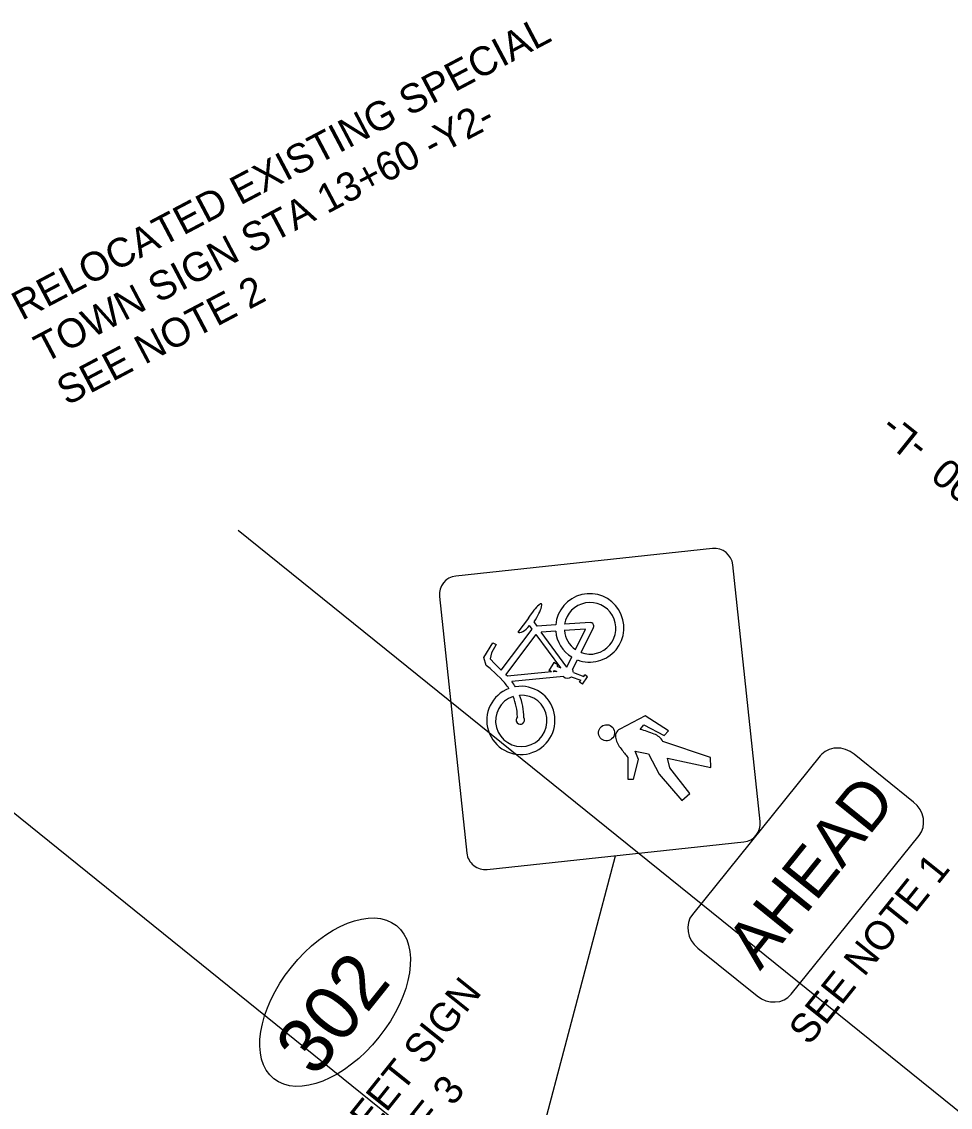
# Model space of a CAD drawing. Extents: x 1487362 to 2061618, y 497428 to 671257.
# Drawn here: x 1488633.1 to 1488736, y 499272.6 to 499392.9 of the extents above; entities that cross this region are included whole.
import ezdxf

# ---------------------------------------------------------------- set-up
doc = ezdxf.new("R2010")
doc.units = 0
for name, color, linetype in [('Exist Sign E', 7, 'Continuous'), ('Exist Sign E Ahead Panel CELL', 7, 'Continuous'), ('Exist Support 1', 7, 'Continuous'), ('Prop Sign E', 7, 'Continuous'), ('Prop Sign E Object Marker CELL', 7, 'Continuous'), ('Scratch_Level_1', 7, 'Continuous'), ('Text', 7, 'Continuous')]:
    doc.layers.add(name, color=color, linetype=linetype)

msp = doc.modelspace()

# ---------------------------------------------------------------- linework, layer by layer
at = {"layer": 'Exist Sign E'}
for p, q in [((1488709.62, 499334.49), (1488681.17, 499331.44)), ((1488714.92, 499304.23), (1488711.87, 499332.68)), ((1488679.36, 499329.19), (1488682.41, 499300.74)), ((1488689.22, 499326.79), (1488688.05, 499325.24)), ((1488689.65, 499325.57), (1488689.34, 499325.97)), ((1488690.2, 499325.9), (1488689.88, 499326.37)), ((1488692.25, 499326.04), (1488690.2, 499325.9)), ((1488696.07, 499326.29), (1488693.23, 499326.1)), ((1488695.07, 499322.97), (1488696.43, 499325.75)), ((1488686.22, 499321.01), (1488689.65, 499325.57)), ((1488686.73, 499320.51), (1488690.09, 499324.97)), ((1488692.81, 499321.28), (1488690.09, 499324.97)), ((1488692.26, 499325.35), (1488690.62, 499325.24)), ((1488693.47, 499321.36), (1488690.62, 499325.24)), ((1488695.56, 499325.57), (1488693.2, 499325.41)), ((1488694.43, 499323.3), (1488695.56, 499325.57)), ((1488684.3, 499322.43), (1488685.29, 499324.04)), ((1488685.64, 499323.86), (1488685.13, 499322.92)), ((1488685.29, 499324.04), (1488685.64, 499323.86)), ((1488684.56, 499321.54), (1488684.3, 499322.43)), ((1488685.13, 499322.92), (1488684.97, 499322.27)), ((1488684.97, 499322.27), (1488685.5, 499321.7)), ((1488693.48, 499321.36), (1488694.04, 499322.49)), ((1488694.12, 499321.09), (1488694.67, 499322.16)), ((1488685, 499321.19), (1488684.56, 499321.54)), ((1488686.24, 499320), (1488685, 499321.19)), ((1488686.22, 499321.01), (1488685.5, 499321.7)), ((1488691.8, 499320.82), (1488691.5, 499321.01)), ((1488691.73, 499320.86), (1488691.5, 499321.01)), ((1488692.06, 499321.85), (1488691.52, 499321)), ((1488692.08, 499320.99), (1488691.96, 499320.82)), ((1488692.38, 499320.87), (1488691.96, 499320.82)), ((1488692.48, 499321.6), (1488692.06, 499321.85)), ((1488692.07, 499320.99), (1488692.38, 499320.87)), ((1488692.49, 499321.6), (1488692.37, 499321.44)), ((1488692.37, 499321.44), (1488692.8, 499321.28)), ((1488686.92, 499320.34), (1488686.73, 499320.51)), ((1488691.8, 499320.82), (1488686.91, 499320.35)), ((1488693.1, 499320.32), (1488687.4, 499319.77)), ((1488693.98, 499320.28), (1488695.05, 499319.9)), ((1488694.21, 499320.75), (1488695.35, 499320.32)), ((1488694.9, 499319.69), (1488695.05, 499319.9)), ((1488695.23, 499319.46), (1488694.9, 499319.69)), ((1488695.23, 499319.46), (1488695.79, 499320.28)), ((1488695.35, 499320.32), (1488695.46, 499320.5)), ((1488695.79, 499320.28), (1488695.46, 499320.5)), ((1488684.66, 499298.93), (1488713.11, 499301.98))]:
    msp.add_line(p, q, dxfattribs=at)
for points in [[(1488701.62, 499314.43), (1488702.03, 499314.94), (1488704.26, 499313.78), (1488704.73, 499314.28), (1488702.17, 499315.97), (1488699.35, 499314.47)], [(1488700.24, 499311.35), (1488700.23, 499308.94), (1488700.88, 499308.92), (1488701.44, 499311.12), (1488701.04, 499312.03), (1488702.53, 499311.76), (1488703.71, 499309.49), (1488706.21, 499306.59), (1488707.12, 499307.34), (1488704.88, 499310.18), (1488704.62, 499311.28), (1488709.44, 499310.23), (1488709.4, 499311.35), (1488704.11, 499313.12)]]:
    msp.add_lwpolyline(points, dxfattribs=at)
for centre, radius, start, end in [((1488709.84, 499332.46), 2.04, 6.1161, 96.1161), ((1488681.39, 499329.41), 2.04, 96.1161, 186.1161), ((1488696.02, 499325.7), 3.79, 248.839, 174.8468), ((1488696.06, 499325.65), 2.86, 249.4542, 170.8979), ((1488696.1, 499325.91), 0.375, 333.8461, 93.8282), ((1488696.02, 499325.7), 3.79, 185.3481, 238.2433), ((1488696.06, 499325.65), 2.86, 184.8373, 235.3657), ((1488693.57, 499320.76), 0.637, 359.8177, 30.2931), ((1488682.16, 499315.81), 5.84, 33.0029, 45.7323), ((1488682.16, 499315.81), 6.56, 30.962, 37.1087), ((1488693.57, 499320.76), 0.637, 222.9807, 310.8196), ((1488688.39, 499315.45), 3.78, 110.6416, 99.1992), ((1488688.44, 499315.4), 2.85, 108.533, 93.6979), ((1488682.16, 499315.81), 5.84, 0.362, 23.0874), ((1488682.16, 499315.81), 6.56, 359.5723, 21.7588), ((1488688.33, 499315.5), 0.471, 133.5219, 32.8623), ((1488712.89, 499304.01), 2.04, 276.1161, 6.1161), ((1488684.44, 499300.96), 2.04, 186.1161, 276.1161)]:
    msp.add_arc(centre, radius, start, end, dxfattribs=at)
for centre, major_axis, ratio, start_param, end_param in [((1488689.54, 499326.57), (1.14, 1.79), 0.185356, 4.712389, 7.853982), ((1488688.87, 499326.33), (0.83, 1.1), 0.433994, 3.141593, 4.712389), ((1488699.74, 499313.69), (-0.683, 0.551), 0.999989, 5.856088, 7.245133), ((1488699.93, 499306.7), (-6.16, 4.97), 0.999989, 4.973098, 5.17626), ((1488702.55, 499312.24), (1.4, -1.13), 0.999989, 1.193544, 1.911048), ((1488701.5, 499314.08), (-2.08, 1.68), 0.999989, 0.918357, 1.400152), ((1488716.72, 499324.96), (-16.64, 13.42), 0.999989, 1.312025, 1.368782)]:
    msp.add_ellipse(centre, major_axis=major_axis, ratio=ratio, start_param=start_param, end_param=end_param, dxfattribs=at)
msp.add_ellipse((1488697.88, 499314.08), major_axis=(0.696, -0.561), ratio=0.999989, dxfattribs=at)
at = {"layer": 'Exist Sign E Ahead Panel CELL'}
for p, q in [((1488721.56, 499311.51), (1488707.4, 499293.94)), ((1488731.89, 499306.4), (1488725.33, 499311.7)), ((1488718.34, 499285.12), (1488732.51, 499302.68)), ((1488708.01, 499290.23), (1488714.58, 499284.93))]:
    msp.add_line(p, q, dxfattribs=at)
for centre, start_param, end_param in [((1488723.75, 499309.75), 1.570796, 3.141593), ((1488730.32, 499304.45), 0, 1.570796), ((1488709.58, 499292.18), 3.141593, 4.712389), ((1488716.15, 499286.88), 4.712389, 6.283185)]:
    msp.add_ellipse(centre, major_axis=(2.19, -1.77), ratio=0.891297, start_param=start_param, end_param=end_param, dxfattribs=at)
at = {"layer": 'Exist Support 1'}
msp.add_line((1488677.29, 499219.07), (1488698.88, 499300.46), dxfattribs=at)
at = {"layer": 'Prop Sign E'}
msp.add_ellipse((1488667.81, 499284.23), major_axis=(6.79, 8.49), ratio=0.571429, dxfattribs=at)
at = {"layer": 'Scratch_Level_1'}
for p, q in [((1488657.05, 499336.52), (1488968.42, 499085.42)), ((1488943.31, 499054.29), (1488631.94, 499305.39))]:
    msp.add_line(p, q, dxfattribs=at)

# ---------------------------------------------------------------- texts
at = {"layer": 'Exist Sign E Ahead Panel CELL'}
msp.add_text('AHEAD', height=5.272, rotation=51.1156, dxfattribs=at).set_placement((1488714.89, 499287.63))
at = {"layer": 'Prop Sign E'}
msp.add_text('302', height=6.136, rotation=51.3436, dxfattribs=at).set_placement((1488665.59, 499275.77))
at = {"layer": 'Prop Sign E Object Marker CELL'}
msp.add_text('STA. 23+90  -L-', height=3.2, rotation=141.2915, dxfattribs=at).set_placement((1488753.34, 499330.54))
at = {"layer": 'Text'}
for s, rotation, p in [('RELOCATED EXISTING SPECIAL ', 27.8351, (1488633.1, 499359.71)), ('TOWN SIGN STA 13+60 -Y2-', 27.8351, (1488635.59, 499354.99)), ('SEE NOTE 2', 27.8351, (1488638.08, 499350.28)), ('SEE NOTE 1', 51.3435, (1488720.33, 499279.32)), ('PROPOSED NEW STREET SIGN', 51.3435, (1488643.48, 499234.42)), ('STA. 11+40 -Y2- SEE NOTE 3', 51.3435, (1488645.87, 499228.87))]:
    msp.add_text(s, height=3.2, rotation=rotation, dxfattribs=at).set_placement(p)

doc.saveas('drawing.dxf')
